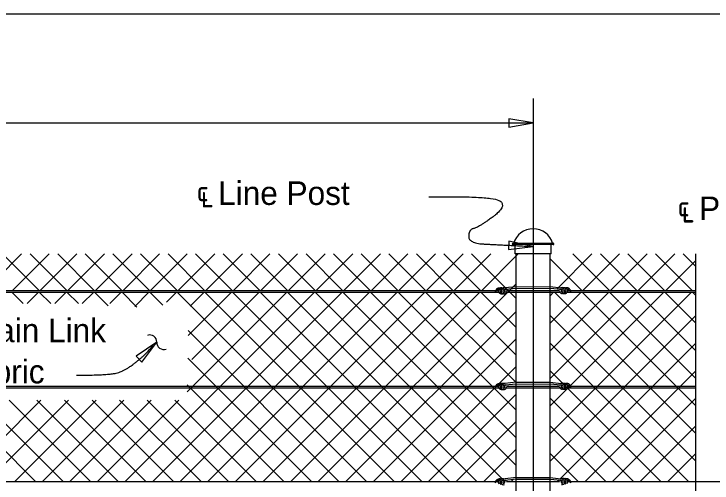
# Model space of a CAD drawing. Extents: x 0 to 41.1, y 0 to 26.4.
# Drawn here: x 17.77 to 23.73, y 22.39 to 26.4 of the extents above; entities that cross this region are included whole.
import ezdxf

# ---------------------------------------------------------------- set-up
doc = ezdxf.new("R2010")
doc.units = 0
for name, color, linetype in [('CL_Major', 7, 'Continuous'), ('Dimension', 7, 'Continuous'), ('Miscellaneous', 7, 'Continuous'), ('Miscellaneous1', 7, 'Continuous'), ('SteelMisc', 7, 'Continuous'), ('SteelMisc_h', 7, 'Continuous'), ('TextStructures', 7, 'Continuous')]:
    doc.layers.add(name, color=color, linetype=linetype)

msp = doc.modelspace()

# ---------------------------------------------------------------- linework, layer by layer
at = {"layer": 'CL_Major'}
msp.add_line((22.2062, 25.6784), (22.2062, 14.8312), dxfattribs=at)
at = {"layer": 'Dimension'}
msp.add_line((2.2062, 25.4682), (22.2062, 25.4682), dxfattribs=at)
for points in [[(22.2062, 25.4682), (21.998, 25.5035), (21.998, 25.4329)], [(22.2064, 24.4121), (22.0003, 24.4587), (21.9965, 24.3883)], [(18.9917, 23.5942), (18.8164, 23.4764), (18.865, 23.4252)]]:
    msp.add_lwpolyline(points, close=True, dxfattribs=at)
msp.add_lwpolyline([(23.5932, 24.349), (23.5932, 21.1819), (23.6966, 21.1819), (23.5932, 21.1369), (23.4899, 21.0919), (23.5932, 21.0919), (23.5932, 20.1983)], dxfattribs=at)
for centre, start, end in [((18.9315, 23.597), 357.71778, 109.44499), ((19.0506, 23.5923), 177.71778, 289.44499)]:
    msp.add_arc(centre, 0.0596, start, end, dxfattribs=at)
for points in [[(21.3168, 24.8359), (21.8626, 24.8457), (21.985, 24.7568), (21.7408, 24.5755), (21.6559, 24.5571), (21.6559, 24.4393), (21.934, 24.427), (22.2063, 24.4121)], [(18.3063, 23.3125), (18.5965, 23.3125), (18.7331, 23.3573), (18.9201, 23.5109), (18.9585, 23.5685)]]:
    msp.add_open_spline(points, degree=2, dxfattribs=at)
at = {"layer": 'Miscellaneous'}
for p, q in [((17.5245, 24.0365), (17.837, 24.349)), ((17.6736, 24.349), (17.9861, 24.0365)), ((17.7602, 24.0365), (18.0727, 24.349)), ((17.9093, 24.349), (18.2218, 24.0365)), ((17.9959, 24.0365), (18.3084, 24.349)), ((18.145, 24.349), (18.4575, 24.0365)), ((18.2316, 24.0365), (18.5441, 24.349)), ((18.3807, 24.349), (18.6932, 24.0365)), ((18.4673, 24.0365), (18.7799, 24.349)), ((18.6164, 24.349), (18.9289, 24.0365)), ((18.703, 24.0365), (19.0156, 24.349)), ((18.8521, 24.349), (19.1646, 24.0365)), ((18.9387, 24.0365), (19.2513, 24.349)), ((19.0878, 24.349), (19.4003, 24.0365)), ((19.1744, 24.0365), (19.487, 24.349)), ((19.3235, 24.349), (19.636, 24.0365)), ((19.4101, 24.0365), (19.7227, 24.349)), ((19.5592, 24.349), (19.8717, 24.0365)), ((19.6458, 24.0365), (19.9584, 24.349)), ((19.7949, 24.349), (20.1074, 24.0365)), ((19.8815, 24.0365), (20.1941, 24.349)), ((20.0306, 24.349), (20.3431, 24.0365)), ((20.1172, 24.0365), (20.4298, 24.349)), ((20.2663, 24.349), (20.5788, 24.0365)), ((20.3529, 24.0365), (20.6655, 24.349)), ((20.502, 24.349), (20.8145, 24.0365)), ((20.5886, 24.0365), (20.9012, 24.349)), ((20.7377, 24.349), (21.0502, 24.0365)), ((20.8243, 24.0365), (21.1369, 24.349)), ((20.9734, 24.349), (21.2859, 24.0365)), ((21.06, 24.0365), (21.3726, 24.349)), ((21.2091, 24.349), (21.5216, 24.0365)), ((21.2957, 24.0365), (21.6083, 24.349)), ((21.4448, 24.349), (21.7573, 24.0365)), ((21.5314, 24.0365), (21.844, 24.349)), ((21.6805, 24.349), (22.0604, 23.9692)), ((21.7671, 24.0365), (22.0797, 24.349)), ((22.4077, 24.048), (22.7088, 24.349)), ((22.5453, 24.349), (22.8578, 24.0365)), ((22.6319, 24.0365), (22.9445, 24.349)), ((22.781, 24.349), (23.0935, 24.0365)), ((22.8676, 24.0365), (23.1802, 24.349)), ((23.0167, 24.349), (23.3292, 24.0365)), ((23.1033, 24.0365), (23.4159, 24.349)), ((23.2524, 24.349), (23.5649, 24.0365)), ((23.4881, 24.349), (23.5932, 24.2439)), ((22.3521, 24.3066), (22.6221, 24.0365)), ((23.339, 24.0365), (23.5932, 24.2907)), ((20.3711, 22.4048), (22.0604, 24.094)), ((22.5076, 24.0365), (22.5121, 24.041)), ((17.7524, 24.0218), (17.85, 23.9241)), ((17.8835, 23.9241), (17.9812, 24.0218)), ((17.9881, 24.0218), (18.0857, 23.9241)), ((18.1192, 23.9241), (18.2169, 24.0218)), ((18.2238, 24.0218), (18.3214, 23.9241)), ((18.3549, 23.9241), (18.4526, 24.0218)), ((18.4595, 24.0218), (18.5763, 23.9049)), ((18.5906, 23.9241), (18.6883, 24.0218)), ((18.6952, 24.0218), (18.8216, 23.8953)), ((18.8028, 23.9006), (18.924, 24.0218)), ((18.9309, 24.0218), (19.0418, 23.9108)), ((18.9569, 22.4048), (20.5739, 24.0218)), ((19.0752, 23.9373), (19.1597, 24.0218)), ((19.1666, 24.0218), (20.7836, 22.4048)), ((19.1926, 22.4048), (20.8096, 24.0218)), ((19.2506, 23.1699), (20.1025, 24.0218)), ((19.2506, 22.9342), (20.3382, 24.0218)), ((19.2609, 23.6515), (19.6311, 24.0218)), ((19.2761, 23.9025), (19.3954, 24.0218)), ((19.2906, 23.4456), (19.8668, 24.0218)), ((19.4023, 24.0218), (21.0193, 22.4048)), ((19.4283, 22.4048), (21.0453, 24.0218)), ((19.638, 24.0218), (21.255, 22.4048)), ((19.664, 22.4048), (21.281, 24.0218)), ((19.8737, 24.0218), (21.4907, 22.4048)), ((19.8997, 22.4048), (21.5167, 24.0218)), ((20.1094, 24.0218), (21.7264, 22.4048)), ((20.1354, 22.4048), (21.7524, 24.0218)), ((20.3451, 24.0218), (21.9407, 22.4262)), ((20.5808, 24.0218), (22.0604, 22.5421)), ((20.8165, 24.0218), (22.0604, 22.7779)), ((21.0522, 24.0218), (22.0604, 23.0136)), ((21.2879, 24.0218), (22.0604, 23.2493)), ((21.5236, 24.0218), (22.0604, 23.485)), ((21.7593, 24.0218), (22.0604, 23.7207)), ((22.3521, 22.8138), (23.56, 24.0218)), ((22.3521, 23.0495), (23.3243, 24.0218)), ((22.3521, 23.2852), (23.0886, 24.0218)), ((22.3521, 23.5209), (22.8529, 24.0218)), ((22.3521, 23.7566), (22.6172, 24.0218)), ((22.3521, 23.9923), (22.3815, 24.0218)), ((22.3884, 24.0218), (23.5931, 22.817)), ((22.6241, 24.0218), (23.5931, 23.0527)), ((22.8598, 24.0218), (23.5931, 23.2884)), ((23.0955, 24.0218), (23.5931, 23.5241)), ((23.3312, 24.0218), (23.5931, 23.7598)), ((23.5669, 24.0218), (23.5931, 23.9955)), ((20.6068, 22.4048), (22.0604, 23.8583)), ((22.3521, 23.8224), (23.5931, 22.5813)), ((22.3521, 22.5781), (23.5932, 23.8193)), ((19.2586, 23.6941), (20.5479, 22.4048)), ((20.8425, 22.4048), (22.0604, 23.6226)), ((22.3521, 23.5867), (23.534, 22.4048)), ((22.4378, 22.4282), (23.5932, 23.5836)), ((19.2574, 23.4595), (20.3122, 22.4048)), ((21.0782, 22.4048), (22.0604, 23.3869)), ((22.3521, 23.351), (23.2983, 22.4048)), ((22.6501, 22.4048), (23.5932, 23.3479)), ((19.2506, 23.2306), (20.0765, 22.4048)), ((22.5078, 23.219), (22.5123, 23.2235)), ((21.3139, 22.4048), (22.0604, 23.1512)), ((17.26, 23.0999), (17.9551, 22.4048)), ((17.307, 22.4048), (18.0021, 23.0999)), ((17.4957, 23.0999), (18.1908, 22.4048)), ((17.5427, 22.4048), (18.2378, 23.0999)), ((17.7314, 23.0999), (18.4265, 22.4048)), ((17.7784, 22.4048), (18.4735, 23.0999)), ((17.9671, 23.0999), (18.6623, 22.4048)), ((18.0141, 22.4048), (18.7092, 23.0999)), ((18.2028, 23.0999), (18.898, 22.4048)), ((18.2498, 22.4048), (18.9449, 23.0999)), ((18.4385, 23.0999), (19.1337, 22.4048)), ((18.4855, 22.4048), (19.1806, 23.0999)), ((18.6742, 23.0999), (19.3694, 22.4048)), ((18.7212, 22.4048), (19.4163, 23.0999)), ((18.9099, 23.0999), (19.6051, 22.4048)), ((19.1456, 23.0999), (19.8408, 22.4048)), ((22.3521, 23.1153), (23.0626, 22.4048)), ((22.8858, 22.4048), (23.5932, 23.1122)), ((21.5496, 22.4048), (22.0604, 22.9155)), ((22.3521, 22.8796), (22.8269, 22.4048)), ((23.1215, 22.4048), (23.5931, 22.8764)), ((21.7853, 22.4048), (22.0604, 22.6798)), ((22.3521, 22.6439), (22.5912, 22.4048)), ((23.3572, 22.4048), (23.5931, 22.6407)), ((22.0527, 22.4364), (22.0604, 22.4441)), ((21.9567, 22.4102), (21.9654, 22.4015)), ((22.021, 22.4048), (22.0367, 22.4204)), ((22.3521, 22.4082), (22.3555, 22.4048)), ((22.4144, 22.4048), (22.4264, 22.4168)), ((23.5929, 22.4048), (23.5932, 22.4051))]:
    msp.add_line(p, q, dxfattribs=at)
at = {"layer": 'Miscellaneous1'}
msp.add_lwpolyline([(0, 26.4), (41.0667, 26.4), (41.0667, 0), (0, 0)], close=True, dxfattribs=at)
at = {"layer": 'SteelMisc'}
for p, q in [((22.0339, 24.441), (22.3785, 24.441)), ((22.3785, 24.4288), (22.0339, 24.4288)), ((22.0521, 24.349), (22.0521, 24.4288)), ((22.3602, 24.349), (22.3602, 24.4288)), ((22.3602, 24.349), (22.0521, 24.349)), ((22.0604, 17.8646), (22.0604, 24.349)), ((22.3521, 17.8646), (22.3521, 24.349)), ((12.5051, 24.0365), (21.8852, 24.0365)), ((21.8951, 24.0365), (21.9083, 24.0365)), ((22.0603, 24.0691), (21.9655, 24.058)), ((22.0603, 24.0546), (21.9677, 24.0451)), ((21.9782, 24.0365), (22.0603, 24.0365)), ((22.0603, 24.0691), (22.3515, 24.0708)), ((22.0603, 24.0546), (22.3515, 24.0563)), ((22.3515, 24.0708), (22.4458, 24.0597)), ((22.3515, 24.0563), (22.4437, 24.0469)), ((22.352, 24.0365), (22.4324, 24.0365)), ((22.5028, 24.0365), (22.518, 24.0365)), ((22.5265, 24.0365), (23.5931, 24.0365)), ((12.5051, 24.0218), (21.9118, 24.0218)), ((21.9767, 24.0218), (22.0603, 24.0218)), ((22.352, 24.0218), (22.4351, 24.0218)), ((22.4978, 24.0218), (23.5931, 24.0218)), ((12.5053, 23.219), (21.8854, 23.219)), ((12.5053, 23.2043), (21.912, 23.2043)), ((21.8953, 23.219), (21.9084, 23.219)), ((22.0605, 23.2516), (21.9656, 23.2405)), ((22.0605, 23.2371), (21.9679, 23.2276)), ((21.9769, 23.2043), (22.0605, 23.2043)), ((21.9783, 23.219), (22.0605, 23.219)), ((22.0605, 23.2516), (22.3517, 23.2533)), ((22.0605, 23.2371), (22.3517, 23.2388)), ((22.3517, 23.2533), (22.446, 23.2422)), ((22.3517, 23.2388), (22.4438, 23.2294)), ((22.3522, 23.219), (22.4326, 23.219)), ((22.3522, 23.2043), (22.4352, 23.2043)), ((22.498, 23.2043), (23.5933, 23.2043)), ((22.5029, 23.219), (22.5182, 23.219)), ((22.5266, 23.219), (23.5933, 23.219)), ((22.0603, 22.4374), (21.9675, 22.4257)), ((22.0603, 22.4229), (21.9675, 22.4132)), ((22.0603, 22.4374), (22.3515, 22.4391)), ((22.0603, 22.4229), (22.3515, 22.4245)), ((22.3515, 22.4391), (22.4435, 22.4275)), ((22.3515, 22.4245), (22.4434, 22.415)), ((12.5265, 22.4048), (21.8852, 22.4048)), ((21.8951, 22.4048), (21.9083, 22.4048)), ((21.9782, 22.4048), (22.0603, 22.4048)), ((22.352, 22.4048), (22.4324, 22.4048)), ((22.5028, 22.4048), (22.518, 22.4048)), ((22.5265, 22.4048), (25.929, 22.4048))]:
    msp.add_line(p, q, dxfattribs=at)
for centre, start, end in [((22.034, 24.4347), 91.1647, 268.8353), ((22.3783, 24.4347), 271.1647, 88.8353)]:
    msp.add_arc(centre, 0.00613, start, end, dxfattribs=at)
for centre, major_axis, ratio, start_param, end_param in [((22.2068, 24.4), (0.1711, 0), 0.957868, 0.252602, 2.888574), ((21.9194, 24.0222), (0.0373, 0), 0.957868, 1.486836, 3.108042), ((21.9405, 23.9825), (-0.0724, 0), 0.957868, 5.162149, 5.652106), ((21.9331, 24.0342), (-0.0249, 0), 0.957868, 6.009018, 7.089857), ((21.9319, 24.0367), (0.023, 0), 0.957868, 1.29026, 2.970541), ((21.9507, 24.0313), (0.0295, 0), 0.957868, 1.220941, 4.039556), ((21.9641, 24.0331), (-0.0303, -0.0108), 0.724765, 4.35367, 6.324556), ((21.9608, 24.029), (-0.0139, 0), 0.957868, 5.22362, 6.905413), ((21.9692, 24.0202), (-0.0259, 0), 0.957868, 4.777514, 5.62749), ((21.9535, 24.0325), (0.0119, 0), 0.957868, 5.725876, 7.416677), ((21.9537, 24.0312), (0.0251, 0), 0.957868, 0.407687, 0.609214), ((22.4572, 24.033), (-0.0251, 0), 0.957868, 5.673972, 5.875498), ((22.4417, 24.022), (0.0259, 0), 0.957868, 0.655696, 1.505671), ((22.4468, 24.0349), (0.0303, -0.0108), 0.724765, 6.241815, 8.212701), ((22.4574, 24.0342), (-0.0119, 0), 0.957868, 5.149694, 6.840495), ((22.4603, 24.0331), (-0.0295, 0), 0.957868, 2.243629, 5.062245), ((22.4501, 24.0308), (0.0139, 0), 0.957868, 5.660958, 7.342751), ((22.479, 24.0385), (-0.023, 0), 0.957868, 3.312645, 4.992926), ((22.4915, 24.024), (-0.0373, 0), 0.957868, 3.175144, 4.79635), ((22.4779, 24.036), (0.0249, 0), 0.957868, 5.476514, 6.557353), ((22.4704, 23.9843), (0.0724, 0), 0.957868, 0.631079, 1.121037), ((21.9344, 24.0302), (0.0231, 0), 0.957868, 3.779554, 4.879821), ((21.9405, 24.0245), (0.0206, -0.0021), 0.798607, 4.32653, 5.220153), ((21.954, 24.0245), (0.0206, -0.0021), 0.798607, 3.333154, 5.220153), ((21.9552, 24.0267), (-0.00795, 0), 0.957868, 6.140374, 9.314262), ((21.9466, 24.0433), (0.0391, 0), 0.957868, 5.082588, 5.41974), ((21.9535, 24.0325), (0.0119, 0), 0.957868, 5.639684, 5.723117), ((21.9537, 24.0312), (0.0251, 0), 0.957868, 5.531357, 6.227833), ((22.4572, 24.033), (-0.0251, 0), 0.957868, 0.055352, 0.751829), ((22.4643, 24.045), (-0.0391, 0), 0.957868, 0.863445, 1.200597), ((22.4574, 24.0342), (-0.0119, 0), 0.957868, 0.560069, 0.643501), ((22.4558, 24.0284), (0.00795, 0), 0.957868, 3.252108, 6.425997), ((22.4569, 24.0263), (-0.0206, -0.0021), 0.798607, 1.063032, 2.950031), ((22.4704, 24.0263), (-0.0206, -0.0021), 0.798607, 1.063032, 1.956656), ((22.4765, 24.032), (-0.0231, 0), 0.957868, 1.403365, 2.503632), ((21.9196, 23.2048), (0.0373, 0), 0.957868, 1.486836, 3.108042), ((21.9407, 23.1651), (-0.0724, 0), 0.957868, 5.162149, 5.652106), ((21.9332, 23.2167), (-0.0249, 0), 0.957868, 6.009018, 7.089857), ((21.9321, 23.2192), (0.023, 0), 0.957868, 1.29026, 2.970541), ((21.9346, 23.2127), (0.0231, 0), 0.957868, 3.779554, 4.879821), ((21.9508, 23.2139), (0.0295, 0), 0.957868, 1.220941, 4.039556), ((21.9643, 23.2157), (-0.0303, -0.0108), 0.724765, 4.35367, 6.324556), ((21.9542, 23.207), (0.0206, -0.0021), 0.798607, 3.333154, 5.220153), ((21.961, 23.2116), (-0.0139, 0), 0.957868, 5.22362, 6.905413), ((21.9553, 23.2092), (-0.00795, 0), 0.957868, 6.140374, 9.314262), ((21.9694, 23.2027), (-0.0259, 0), 0.957868, 4.777514, 5.62749), ((21.9536, 23.215), (0.0119, 0), 0.957868, 5.725876, 7.416677), ((21.9536, 23.215), (0.0119, 0), 0.957868, 5.639684, 5.723117), ((21.9539, 23.2138), (0.0251, 0), 0.957868, 5.531357, 6.227833), ((21.9539, 23.2138), (0.0251, 0), 0.957868, 0.407687, 0.609214), ((22.4574, 23.2155), (-0.0251, 0), 0.957868, 0.055352, 0.751829), ((22.4574, 23.2155), (-0.0251, 0), 0.957868, 5.673972, 5.875498), ((22.4644, 23.2276), (-0.0391, 0), 0.957868, 0.863445, 1.200597), ((22.4469, 23.2174), (0.0303, -0.0108), 0.724765, 6.241815, 8.212701), ((22.4419, 23.2045), (0.0259, 0), 0.957868, 0.655696, 1.505671), ((22.4576, 23.2168), (-0.0119, 0), 0.957868, 5.149694, 6.840495), ((22.4576, 23.2168), (-0.0119, 0), 0.957868, 0.560069, 0.643501), ((22.4559, 23.211), (0.00795, 0), 0.957868, 3.252108, 6.425997), ((22.4571, 23.2088), (-0.0206, -0.0021), 0.798607, 1.063032, 2.950031), ((22.4604, 23.2156), (-0.0295, 0), 0.957868, 2.243629, 5.062245), ((22.4503, 23.2134), (0.0139, 0), 0.957868, 5.660958, 7.342751), ((22.4792, 23.221), (-0.023, 0), 0.957868, 3.312645, 4.992926), ((22.4766, 23.2145), (-0.0231, 0), 0.957868, 1.403365, 2.503632), ((22.4917, 23.2065), (-0.0373, 0), 0.957868, 3.175144, 4.79635), ((22.478, 23.2185), (0.0249, 0), 0.957868, 5.476514, 6.557353), ((22.4705, 23.1668), (0.0724, 0), 0.957868, 0.631079, 1.121037), ((21.9407, 23.207), (0.0206, -0.0021), 0.798607, 4.32653, 5.220153), ((21.9468, 23.2258), (0.0391, 0), 0.957868, 5.082588, 5.41974), ((22.4705, 23.2088), (-0.0206, -0.0021), 0.798607, 1.063032, 1.956656), ((21.9194, 22.3905), (0.0373, 0), 0.957868, 1.427863, 3.108042), ((21.9319, 22.405), (0.023, 0), 0.957868, 1.234085, 2.861055), ((21.9507, 22.3996), (0.0295, 0), 0.957868, 1.132635, 3.996184), ((21.9641, 22.4014), (-0.0303, -0.0108), 0.724765, 4.35367, 6.224248), ((22.4468, 22.4032), (0.0303, -0.0108), 0.724765, 0.058937, 1.929515), ((22.4603, 22.4014), (-0.0295, 0), 0.957868, 2.287002, 5.15055), ((22.479, 22.4067), (-0.023, 0), 0.957868, 3.422131, 5.0491), ((22.4915, 22.3923), (-0.0373, 0), 0.957868, 3.175144, 4.855322), ((21.9405, 22.3508), (-0.0724, 0), 0.957868, 5.133134, 5.652106), ((21.9331, 22.4025), (-0.0249, 0), 0.957868, 5.913851, 7.104804), ((21.954, 22.3928), (0.0206, -0.0021), 0.798607, 3.319436, 5.220153), ((21.9608, 22.3973), (-0.0139, 0), 0.957868, 5.822914, 6.485782), ((21.9552, 22.3949), (-0.00795, 0), 0.957868, 0.039428, 2.999692), ((21.9692, 22.3885), (-0.0259, 0), 0.957868, 4.777514, 5.646371), ((21.9535, 22.4007), (0.0119, 0), 0.957868, 5.725876, 7.416677), ((21.9535, 22.4007), (0.0119, 0), 0.957868, 5.639684, 5.723117), ((21.9537, 22.3995), (0.0251, 0), 0.957868, 0.221743, 0.642584), ((22.4572, 22.4013), (-0.0251, 0), 0.957868, 5.640694, 6.136824), ((22.4417, 22.3902), (0.0259, 0), 0.957868, 0.636815, 1.505671), ((22.4574, 22.4025), (-0.0119, 0), 0.957868, 5.149694, 6.840495), ((22.4574, 22.4025), (-0.0119, 0), 0.957868, 0.560069, 0.643501), ((22.4558, 22.3967), (0.00795, 0), 0.957868, 3.283494, 6.243757), ((22.4569, 22.3945), (-0.0206, -0.0021), 0.798607, 1.063032, 2.96375), ((22.4501, 22.3991), (0.0139, 0), 0.957868, 6.080589, 6.743456), ((22.4779, 22.4042), (0.0249, 0), 0.957868, 5.476514, 6.65252), ((22.4704, 22.3526), (0.0724, 0), 0.957868, 0.631079, 1.150052)]:
    msp.add_ellipse(centre, major_axis=major_axis, ratio=ratio, start_param=start_param, end_param=end_param, dxfattribs=at)
at = {"layer": 'SteelMisc_h'}
for p, q in [((22.0603, 24.0365), (22.352, 24.0365)), ((22.0603, 24.0218), (22.352, 24.0218)), ((22.0605, 23.219), (22.3522, 23.219)), ((22.0605, 23.2043), (22.3522, 23.2043)), ((22.0603, 22.4048), (22.352, 22.4048))]:
    msp.add_line(p, q, dxfattribs=at)

# ---------------------------------------------------------------- texts
at = {"layer": 'Dimension'}
for s, p in [('Chain Link ', (17.2835, 23.5945)), ('Fabric ', (17.2835, 23.2425))]:
    msp.add_text(s, height=0.2016, dxfattribs=at).set_placement(p)
at = {"layer": 'TextStructures'}
for s, p in [('℄ Line Post', (19.3314, 24.7677)), ('℄ Pull Post', (23.4401, 24.6377))]:
    msp.add_text(s, height=0.2016, dxfattribs=at).set_placement(p)

doc.saveas('drawing.dxf')
